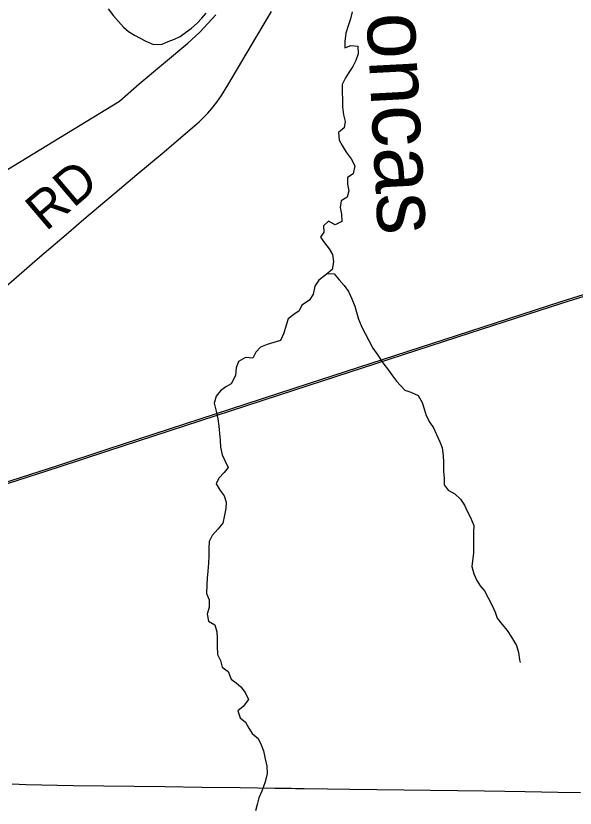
# Model space of a CAD drawing. Extents: x 0 to 34, y 0 to 22.
# Drawn here: x 3.389 to 4.241, y 14.854 to 16.061 of the extents above; entities that cross this region are included whole.
import ezdxf

# ---------------------------------------------------------------- set-up
doc = ezdxf.new("R2010")
doc.units = 0
for name, color, linetype in [('GM_X_County_Road', 7, 'Continuous'), ('GM_X_County_Road_Text', 7, 'Continuous'), ('GM_X_Major_River', 7, 'Continuous'), ('GM_X_Minor_River', 7, 'Continuous'), ('GM_X_Minor_River_Text', 7, 'Continuous'), ('GM_X_Rail_Line', 7, 'Continuous')]:
    doc.layers.add(name, color=color, linetype=linetype)

msp = doc.modelspace()

# ---------------------------------------------------------------- linework, layer by layer
at = {"layer": 'GM_X_County_Road'}
for points in [[(3.3537, 15.6322), (3.4055, 15.6768), (3.4218, 15.6912), (3.4692, 15.7312), (3.4928, 15.7515), (3.5403, 15.7915), (3.5734, 15.8196), (3.6118, 15.8512), (3.6684, 15.8997), (3.6752, 15.906), (3.6815, 15.9127), (3.6876, 15.9198), (3.6951, 15.9296), (3.7022, 15.9397), (3.7123, 15.9553), (3.7564, 16.0303), (3.7785, 16.0677)], [(3.3831, 14.8913), (3.4048, 14.8905), (3.4763, 14.8891), (3.6162, 14.8871), (3.6722, 14.8864), (3.7308, 14.886), (3.7836, 14.885), (3.8086, 14.8847), (3.8152, 14.8844), (3.8284, 14.8843), (3.8642, 14.8836), (3.8979, 14.8835), (4.1032, 14.8809), (4.1654, 14.8799), (4.2151, 14.8788), (4.2494, 14.8781)]]:
    msp.add_lwpolyline(points, dxfattribs=at)
at = {"layer": 'GM_X_Major_River'}
msp.add_lwpolyline([(3.5297, 16.0718), (3.5378, 16.0608), (3.5454, 16.0525), (3.5531, 16.0438), (3.5607, 16.037), (3.5699, 16.0318), (3.587, 16.0224), (3.5989, 16.0175), (3.6122, 16.018), (3.6212, 16.0218), (3.6307, 16.0253), (3.6394, 16.0295), (3.6477, 16.0357), (3.6568, 16.0422), (3.6655, 16.0498), (3.6723, 16.0575), (3.6791, 16.0651)], dxfattribs=at)
at = {"layer": 'GM_X_Minor_River'}
for points in [[(3.9017, 16.0669), (3.8991, 16.0563), (3.8957, 16.0456), (3.892, 16.0345), (3.8902, 16.022), (3.8903, 16.0125), (3.8997, 16.016), (3.9104, 16.0149), (3.9105, 16.0031), (3.9071, 15.9928), (3.9026, 15.9837), (3.8966, 15.9749), (3.8913, 15.9665), (3.8865, 15.9566), (3.8862, 15.9444), (3.8866, 15.9341), (3.8867, 15.9224), (3.8883, 15.9102), (3.891, 15.9003), (3.8892, 15.8904), (3.8809, 15.8832), (3.8817, 15.8718), (3.8864, 15.8634), (3.8925, 15.8532), (3.8998, 15.843), (3.9056, 15.8327), (3.903, 15.8206), (3.8943, 15.8148), (3.8947, 15.8045), (3.8963, 15.7947), (3.8941, 15.7848), (3.8847, 15.7794), (3.8832, 15.7691), (3.8852, 15.7592), (3.8856, 15.7478), (3.8754, 15.7428), (3.8655, 15.7485), (3.8579, 15.7412), (3.8584, 15.7317), (3.8531, 15.7237), (3.8596, 15.7154), (3.8665, 15.7063), (3.8715, 15.6976), (3.8731, 15.6862), (3.8713, 15.6748), (3.8615, 15.6667), (3.8509, 15.6583), (3.8449, 15.6491), (3.842, 15.6373), (3.8367, 15.6278), (3.825, 15.6205), (3.8209, 15.6117), (3.8125, 15.6063), (3.8038, 15.5994), (3.8009, 15.5899), (3.7975, 15.5777)], [(3.864, 15.6687), (3.874, 15.6679), (3.8817, 15.6588), (3.8893, 15.6505), (3.8962, 15.6414), (3.9013, 15.6301), (3.9055, 15.6191), (3.9082, 15.6096), (3.911, 15.599), (3.9168, 15.5861), (3.9214, 15.577), (3.9272, 15.5664), (3.9333, 15.555), (3.9406, 15.5444), (3.9483, 15.5327), (3.9567, 15.5213), (3.9629, 15.5126), (3.969, 15.5047), (3.982, 15.4911), (3.9911, 15.4881), (4.0022, 15.4828), (4.0083, 15.4722), (4.0111, 15.4627), (4.0142, 15.4525), (4.02, 15.4419), (4.0257, 15.4335), (4.0303, 15.4233), (4.035, 15.4123), (4.0385, 15.4032), (4.0404, 15.3914), (4.0409, 15.3808), (4.041, 15.3671), (4.0418, 15.3568), (4.0419, 15.347), (4.048, 15.3386), (4.0583, 15.333), (4.0667, 15.3247), (4.0729, 15.316), (4.0767, 15.3069), (4.0817, 15.297), (4.0868, 15.2849), (4.0864, 15.2754), (4.0865, 15.2636), (4.0866, 15.2533), (4.0867, 15.2431), (4.0842, 15.2225), (4.0869, 15.2111), (4.0915, 15.2013), (4.0965, 15.193), (4.1034, 15.1854), (4.1088, 15.1748), (4.1142, 15.1642), (4.1196, 15.1528), (4.1227, 15.1437), (4.1304, 15.1342), (4.1376, 15.1248), (4.1442, 15.1149), (4.1522, 15.1021), (4.155, 15.0914), (4.1566, 15.0804), (4.1577, 15.0762)], [(3.7975, 15.5777), (3.7923, 15.5667), (3.7824, 15.5636), (3.7722, 15.5604), (3.762, 15.5566), (3.7548, 15.5486), (3.7503, 15.5398), (3.7389, 15.5405), (3.7283, 15.5347), (3.725, 15.5248), (3.7235, 15.5134), (3.7172, 15.5008), (3.7088, 15.4958), (3.7009, 15.49), (3.6945, 15.4816), (3.6912, 15.471), (3.6943, 15.4588), (3.697, 15.4471), (3.6982, 15.436), (3.6991, 15.425), (3.7003, 15.4148), (3.7011, 15.4041), (3.7035, 15.3927), (3.7073, 15.384), (3.7127, 15.373), (3.7063, 15.3654), (3.6984, 15.357), (3.6943, 15.3482), (3.7004, 15.338), (3.7066, 15.33), (3.7093, 15.3205), (3.709, 15.3106), (3.7068, 15.3004), (3.7046, 15.2882), (3.6967, 15.2794), (3.6884, 15.2695), (3.6835, 15.2603), (3.6832, 15.25), (3.6833, 15.2386), (3.6826, 15.2276), (3.6815, 15.2154), (3.6808, 15.2044), (3.6802, 15.1949), (3.6795, 15.1812), (3.6834, 15.1717), (3.6838, 15.1607), (3.6808, 15.15), (3.6824, 15.139), (3.6923, 15.1338), (3.6951, 15.1231), (3.6959, 15.1132), (3.6956, 15.1011), (3.6965, 15.0882), (3.7007, 15.0791), (3.7034, 15.0692), (3.7126, 15.0624), (3.7169, 15.051), (3.7249, 15.0454), (3.7321, 15.039), (3.7387, 15.0306), (3.7433, 15.0196), (3.7354, 15.009), (3.7274, 15.0024), (3.7309, 14.9918), (3.739, 14.9854), (3.744, 14.9763), (3.749, 14.968), (3.7581, 14.9604), (3.7628, 14.9506), (3.7662, 14.9415), (3.769, 14.9293), (3.7713, 14.9183), (3.7718, 14.9073), (3.7688, 14.8943), (3.764, 14.8803), (3.7595, 14.87), (3.7569, 14.8597), (3.754, 14.8505)]]:
    msp.add_lwpolyline(points, dxfattribs=at)
at = {"layer": 'GM_X_Rail_Line'}
for points in [[(2.7297, 15.2056), (2.8397, 15.3372), (2.9885, 15.4804), (3.0212, 15.5034), (3.0552, 15.5228), (3.0833, 15.5374), (3.1093, 15.5614), (3.1376, 15.6046), (3.1635, 15.6602), (3.1788, 15.6862), (3.1987, 15.7084), (3.224, 15.7301), (3.2743, 15.765), (3.5468, 15.9313), (3.5769, 15.9577), (3.6509, 16.0195), (3.6692, 16.0362), (3.6936, 16.0627)], [(3.2088, 15.2971), (3.2684, 15.3142), (3.4536, 15.3739), (3.5291, 15.3985), (3.8359, 15.4986), (4.0815, 15.5782), (4.2209, 15.6235), (4.4575, 15.6975), (4.6896, 15.7766), (4.9157, 15.8481), (5.2297, 15.9517), (5.4604, 16.0265), (5.5567, 16.0607)], [(3.2677, 15.3166), (3.4529, 15.3763), (3.5283, 15.4009), (3.8351, 15.5009), (4.0807, 15.5806), (4.2201, 15.6258), (4.4567, 15.6999)]]:
    msp.add_lwpolyline(points, dxfattribs=at)

# ---------------------------------------------------------------- texts
at = {"layer": 'GM_X_County_Road_Text'}
msp.add_text('RD', height=0.05682, rotation=40.4406, dxfattribs=at).set_placement((3.4348, 15.7318))
at = {"layer": 'GM_X_Minor_River_Text'}
msp.add_text('Poncas', height=0.09475, rotation=273.0016, dxfattribs=at).set_placement((3.9191, 16.1483))

doc.saveas('drawing.dxf')
